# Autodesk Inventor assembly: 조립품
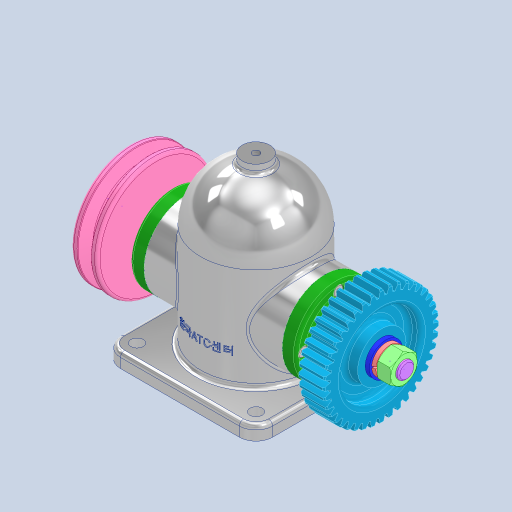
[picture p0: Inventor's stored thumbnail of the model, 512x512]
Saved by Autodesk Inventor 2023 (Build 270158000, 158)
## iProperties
Created: 2025-04
Part Number: 조립품
Document SubType Name: Assembly
Designer: Admin
Author: Admin
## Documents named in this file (14)
- C:\Users\Admin\Desktop\750406V1002\조립품.iam
- C:\Users\Admin\Desktop\750406V1002\본체.ipt
- C:\Users\Admin\Desktop\750406V1002\깊은 홈 볼 베어링 6203.ipt
- C:\Users\Admin\Desktop\750406V1002\축.ipt
- C:\Users\Admin\Desktop\750406V1002\커버.ipt
- C:\Users\Admin\Desktop\750406V1002\오일 실 26 38 8.ipt
- C:\Users\Admin\Desktop\750406V1002\6각 구멍붙이 볼트 M4x12.ipt
- C:\Users\Admin\Desktop\750406V1002\칼라.ipt
- C:\Users\Admin\Desktop\750406V1002\평행 키 5x5x12.ipt
- C:\Users\Admin\Desktop\750406V1002\스퍼기어.ipt
- C:\Users\Admin\Desktop\750406V1002\V 벨트 풀리.ipt
- C:\Users\Admin\Desktop\750406V1002\평와셔 M12.ipt
- C:\Users\Admin\Desktop\750406V1002\스프링 와셔 M12.ipt
- C:\Users\Admin\Desktop\750406V1002\6각 너트 M12x1.ipt
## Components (11 placed, 3 different names)
1. 6각 구멍붙이 볼트 M4x12:1
2. 6각 구멍붙이 볼트 M4x12:2
3. 6각 구멍붙이 볼트 M4x12:3
4. 6각 구멍붙이 볼트 M4x12:4
5. 6각 구멍붙이 볼트 M4x12:5
6. 6각 구멍붙이 볼트 M4x12:6
7. 6각 구멍붙이 볼트 M4x12:7
8. 6각 구멍붙이 볼트 M4x12:8
9. V 벨트 풀리:1
10. 6각 너트 M12x1:1
11. 6각 너트 M12x1:2
